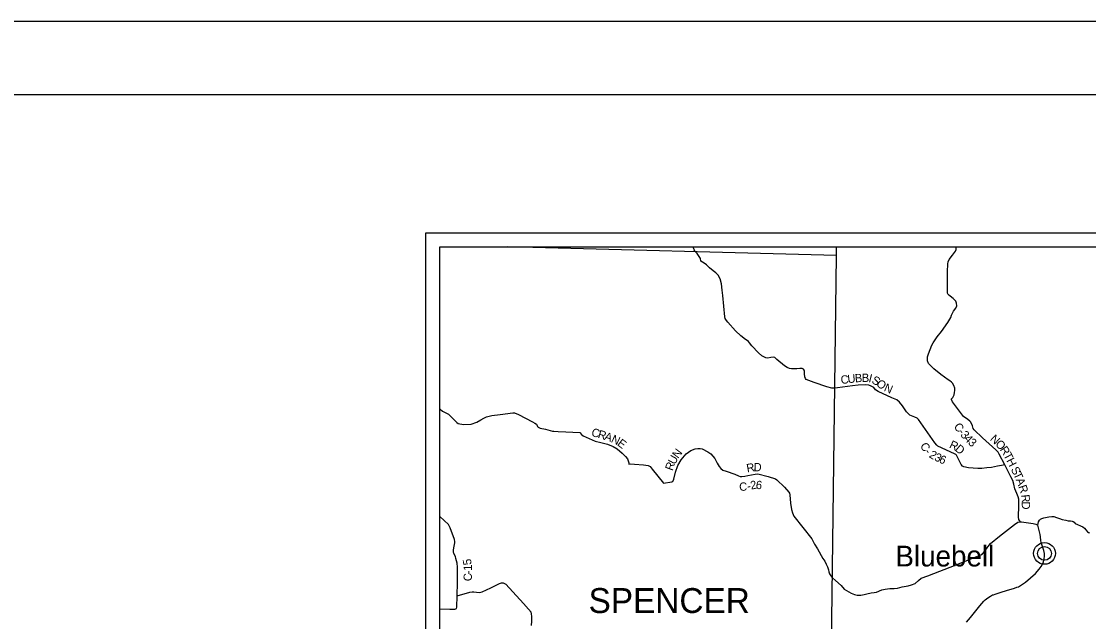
# Model space of a CAD drawing. Extents: x 0 to 34, y 0 to 22.
# Drawn here: x 17 to 24.28, y 17.9 to 22 of the extents above; entities that cross this region are included whole.
import ezdxf

# ---------------------------------------------------------------- set-up
doc = ezdxf.new("R2010")
doc.units = 0
for name, color, linetype in [('Default', 7, 'Continuous'), ('GM_X_County_Road', 7, 'Continuous'), ('GM_X_County_Road_Text', 7, 'Continuous'), ('GM_X_State_Route', 7, 'Continuous'), ('GM_X_Township', 7, 'Continuous'), ('GM_X_Township_Text', 7, 'Continuous'), ('GM_X_Unincorporated', 7, 'Continuous'), ('GM_X_Unincorporated_Text', 7, 'Continuous'), ('SH_Border', 7, 'Continuous'), ('SH_Cut_Line', 7, 'Continuous')]:
    doc.layers.add(name, color=color, linetype=linetype)

msp = doc.modelspace()

# ---------------------------------------------------------------- linework, layer by layer
at = {"layer": 'Default'}
for p, q in [((19.8526, 20.4625), (30.697, 20.4625)), ((19.8526, 9.6182), (19.8526, 20.4625))]:
    msp.add_line(p, q, dxfattribs=at)
msp.add_lwpolyline([(19.7581, 20.557), (30.7915, 20.557), (30.7915, 9.5237), (19.7581, 9.5237)], close=True, dxfattribs=at)
for points in [[(23.1773, 19.6971), (23.1785, 19.7118), (23.1846, 19.7322), (23.2089, 19.7911), (23.2169, 19.8062), (23.2449, 19.847), (23.2733, 19.885), (23.3165, 19.9446), (23.3377, 19.9797), (23.343, 19.9948), (23.3548, 20.0224), (23.3714, 20.0427), (23.3779, 20.0582), (23.3768, 20.0775), (23.3716, 20.0908), (23.3647, 20.0975), (23.3532, 20.1086), (23.3321, 20.1261), (23.3224, 20.1333), (23.3186, 20.1367), (23.3156, 20.1451), (23.3142, 20.161), (23.3142, 20.2018), (23.3142, 20.2911), (23.3163, 20.3448), (23.319, 20.3584), (23.3269, 20.3746), (23.3485, 20.4055), (23.3682, 20.4331), (23.3728, 20.4425), (23.3743, 20.4557), (23.3742, 20.4625)], [(22.5284, 19.4972), (22.527, 19.4972), (22.4928, 19.5061), (22.4048, 19.537), (22.3519, 19.5565), (22.3459, 19.563), (22.3414, 19.5751), (22.3399, 19.5948), (22.3388, 19.613), (22.337, 19.6205), (22.3336, 19.6266), (22.3245, 19.6312), (22.3161, 19.632), (22.3083, 19.6324), (22.2879, 19.6287), (22.2521, 19.6299), (22.2374, 19.6319), (22.2219, 19.638), (22.2035, 19.649), (22.1511, 19.6935), (22.1368, 19.7064), (22.1259, 19.7091), (22.1097, 19.7076), (22.0897, 19.7024), (22.0768, 19.704), (22.049, 19.7181), (22.0252, 19.739), (21.9816, 19.7861), (21.9654, 19.8073), (21.9571, 19.8168), (21.9484, 19.8233), (21.9368, 19.8294), (21.9066, 19.8543), (21.8694, 19.8898), (21.8167, 19.9478), (21.8073, 19.9582), (21.7982, 19.9733), (21.7971, 19.9851), (21.7839, 20.129), (21.7787, 20.165), (21.7731, 20.2089), (21.7637, 20.2438), (21.7513, 20.2673), (21.734, 20.2844), (21.7163, 20.2985), (21.6922, 20.3183), (21.6704, 20.338), (21.6545, 20.3506), (21.6338, 20.3635), (21.6298, 20.3832), (21.6221, 20.3965), (21.6083, 20.4171), (21.5937, 20.4302), (21.5864, 20.4436), (21.5852, 20.4482)], [(23.8134, 18.5861), (23.8049, 18.5953), (23.8004, 18.6025), (23.7982, 18.6176), (23.8007, 18.6962), (23.8005, 18.7397), (23.7975, 18.7571), (23.7878, 18.7787), (23.774, 18.8105), (23.7665, 18.8427), (23.7594, 18.868), (23.746, 18.8938), (23.7047, 18.9744), (23.6666, 19.048), (23.6599, 19.0616), (23.6433, 19.0768), (23.5531, 19.1595), (23.496, 19.2127), (23.4897, 19.2229), (23.4844, 19.2396), (23.4732, 19.2661), (23.4672, 19.2733), (23.4522, 19.2832), (23.424, 19.3052), (23.3497, 19.4038), (23.3426, 19.4193), (23.343, 19.4242), (23.3505, 19.4344), (23.3604, 19.4518), (23.3631, 19.468), (23.3639, 19.4809), (23.3636, 19.4975), (23.3572, 19.5168), (23.3486, 19.5312), (23.3422, 19.5392), (23.3317, 19.5468), (23.3189, 19.5536), (23.2681, 19.5897), (23.2208, 19.6304), (23.1858, 19.6657), (23.178, 19.6842), (23.1773, 19.6971)], [(23.7047, 18.9744), (23.6833, 18.9704), (23.6546, 18.9656), (23.6143, 18.9567), (23.5818, 18.9534), (23.5479, 18.9497), (23.5211, 18.9502), (23.4586, 18.955), (23.425, 18.9619), (23.4171, 18.9657), (23.4074, 18.976), (23.3913, 19.0097), (23.3804, 19.032), (23.3756, 19.0404), (23.3707, 19.0453), (23.3616, 19.0502), (23.2495, 19.1017), (23.2412, 19.1085), (23.2281, 19.1252), (23.1159, 19.2848), (23.1069, 19.292), (23.0919, 19.2993), (23.0572, 19.3145), (23.0347, 19.335), (23.0088, 19.376), (22.9882, 19.4029), (22.9698, 19.4188), (22.9347, 19.4314), (22.8417, 19.4737), (22.8237, 19.4865), (22.8119, 19.5011), (22.7934, 19.5123), (22.7788, 19.5174), (22.7547, 19.5196), (22.7048, 19.5179), (22.6678, 19.514), (22.5657, 19.4994), (22.5455, 19.4972), (22.5284, 19.4972)], [(19.8526, 19.3572), (19.8552, 19.3539), (19.8715, 19.3411), (19.8953, 19.3303), (19.9135, 19.3198), (19.9382, 19.2957), (19.9683, 19.2637), (19.9788, 19.2576), (20.0144, 19.2503), (20.0665, 19.2514), (20.1049, 19.2652), (20.1338, 19.2817), (20.1526, 19.2935), (20.1707, 19.3016), (20.2068, 19.3113), (20.2657, 19.3169), (20.3513, 19.3295), (20.3633, 19.3288), (20.3895, 19.318), (20.4849, 19.2671), (20.502, 19.2589), (20.5114, 19.2521), (20.5202, 19.2362), (20.5233, 19.2306), (20.538, 19.2242), (20.5736, 19.218), (20.6061, 19.2095), (20.6205, 19.2043), (20.6307, 19.2036), (20.6612, 19.203), (20.7118, 19.2006), (20.8085, 19.1944), (20.8184, 19.182), (20.8305, 19.1722), (20.8718, 19.1543), (20.9126, 19.1371), (20.9516, 19.1275), (20.9958, 19.1164), (21.0359, 19.1003), (21.0617, 19.0838), (21.0963, 19.0541), (21.1194, 19.0323), (21.1331, 19.0157), (21.1424, 18.9889), (21.1424, 18.9795), (21.1501, 18.9803), (21.1806, 18.9782), (21.2417, 18.9755), (21.2731, 18.9711), (21.2875, 18.9633), (21.3019, 18.9452), (21.3777, 18.8502), (21.4358, 18.8581), (21.4418, 18.8616), (21.4488, 18.8771), (21.4606, 18.9234), (21.4769, 18.9708), (21.4989, 19.008), (21.5333, 19.0502), (21.5637, 19.0724), (21.5938, 19.0846), (21.6133, 19.087), (21.6284, 19.087), (21.6409, 19.0831), (21.6808, 19.0626), (21.7015, 19.0489), (21.7158, 19.0344), (21.7282, 19.017), (21.7444, 18.9863), (21.7576, 18.9635), (21.7688, 18.9506), (21.7835, 18.9377), (21.8065, 18.9308), (21.8653, 18.9113), (21.8894, 18.9006), (21.9004, 18.8953), (21.9124, 18.8941), (21.9332, 18.8967), (21.9532, 18.9011), (22.0023, 18.9104), (22.0226, 18.9122), (22.0913, 18.8957), (22.1429, 18.8785), (22.152, 18.8732), (22.2032, 18.8227), (22.2325, 18.7889), (22.2381, 18.7805), (22.24, 18.7703), (22.2433, 18.7135), (22.2511, 18.6688), (22.2578, 18.6461), (22.2672, 18.6253), (22.3887, 18.4691), (22.4076, 18.4345), (22.4274, 18.4006), (22.4648, 18.3353), (22.4774, 18.3175), (22.4881, 18.2976), (22.4964, 18.2783), (22.5022, 18.2584), (22.5062, 18.244), (22.5111, 18.232), (22.5197, 18.2182), (22.5285, 18.2069), (22.5305, 18.2048)], [(19.972, 18.0798), (19.9729, 18.1729), (19.9744, 18.2758), (19.9712, 18.3038), (19.963, 18.3363), (19.9592, 18.3496), (19.9492, 18.3692), (19.9465, 18.3801), (19.9457, 18.3915), (19.9497, 18.4093), (19.9563, 18.4419), (19.9558, 18.4517), (19.9531, 18.4657), (19.9242, 18.5454), (19.9177, 18.5594), (19.9116, 18.5677), (19.8535, 18.6226), (19.8526, 18.6234)], [(22.5305, 18.2048), (22.5502, 18.1846), (22.5886, 18.1507), (22.6094, 18.1263), (22.6585, 18.0995), (22.6816, 18.0902), (22.6981, 18.0856), (22.7096, 18.0849), (22.7231, 18.086), (22.7473, 18.0906), (22.7657, 18.0956), (22.7953, 18.1014), (22.8153, 18.1037), (22.8302, 18.1068), (22.8671, 18.121), (22.889, 18.1267), (22.9213, 18.13), (22.9505, 18.13), (22.9727, 18.1338), (23.005, 18.1415), (23.0472, 18.1492), (23.0703, 18.1554), (23.0933, 18.1653), (23.1164, 18.1861), (23.1356, 18.2022), (23.1801, 18.2181), (23.3733, 18.2929), (23.5428, 18.3607), (23.5534, 18.3675), (23.5682, 18.3845), (23.5853, 18.408), (23.592, 18.4173), (23.6075, 18.4376), (23.6695, 18.4888), (23.7724, 18.5686), (23.7939, 18.5836), (23.8045, 18.5866), (23.8134, 18.5861)], [(23.8134, 18.5861), (23.8199, 18.5858), (23.8991, 18.5742)], [(23.8991, 18.5742), (23.8994, 18.5741), (23.9167, 18.5699), (23.9315, 18.5627)], [(19.8526, 17.9925), (19.9217, 17.9902), (19.9462, 17.9899), (19.9564, 17.9904), (19.9624, 17.9919), (19.9665, 17.9953), (19.9695, 18.0029), (19.972, 18.0798), (20.0586, 18.1049), (20.0733, 18.108), (20.085, 18.1073), (20.1039, 18.1059), (20.1254, 18.1038), (20.1428, 18.1076), (20.2018, 18.1349), (20.2609, 18.1647), (20.2729, 18.1697), (20.285, 18.169), (20.3024, 18.1601), (20.3515, 18.1089), (20.4241, 18.0291), (20.4579, 17.9903), (20.4762, 17.9703)], [(20.4777, 17.878), (20.4804, 17.909), (20.4811, 17.94), (20.4783, 17.9589), (20.4762, 17.9703)]]:
    msp.add_lwpolyline(points, dxfattribs=at)
at = {"layer": 'GM_X_County_Road'}
msp.add_lwpolyline([(21.5852, 20.4482), (21.5833, 20.455), (21.5816, 20.4625)], dxfattribs=at)
at = {"layer": 'GM_X_State_Route'}
msp.add_lwpolyline([(23.4452, 17.9024), (23.4705, 17.9333), (23.4988, 17.967), (23.5361, 18.0129), (23.5614, 18.0438), (23.5715, 18.0542), (23.5902, 18.068), (23.6083, 18.0796), (23.6218, 18.0866), (23.6281, 18.0888), (23.6395, 18.0928), (23.6809, 18.1066), (23.7178, 18.1169), (23.771, 18.133), (23.7883, 18.1389), (23.7988, 18.1432), (23.8135, 18.1525), (23.8461, 18.1748), (23.8817, 18.2029), (23.9138, 18.2339), (23.9392, 18.2622), (23.953, 18.2806), (23.9619, 18.2962), (23.9684, 18.3133), (23.9739, 18.3327), (23.9767, 18.3513), (23.9761, 18.3706), (23.9713, 18.3898), (23.9599, 18.4249), (23.954, 18.4445), (23.9519, 18.4578), (23.9497, 18.4827), (23.9465, 18.4986), (23.9417, 18.5171), (23.9342, 18.5458), (23.9315, 18.5627), (23.932, 18.5742), (23.9352, 18.5855), (23.9419, 18.5966), (23.9486, 18.6046), (23.9573, 18.6089), (23.9723, 18.6133), (24.0067, 18.619), (24.0252, 18.6222), (24.0392, 18.6216), (24.0582, 18.6158), (24.0783, 18.6081), (24.0965, 18.6026), (24.1215, 18.5968), (24.1375, 18.5936), (24.1534, 18.5919), (24.1644, 18.5902), (24.1712, 18.5876), (24.1777, 18.5824), (24.1861, 18.5749), (24.2017, 18.5664), (24.2219, 18.5583), (24.2371, 18.5509), (24.2478, 18.5427), (24.2581, 18.5303), (24.2681, 18.5183), (24.275, 18.5138), (24.2833, 18.5102)], dxfattribs=at)
at = {"layer": 'GM_X_Township'}
for p, q in [((22.5575, 20.4019), (20.3145, 20.4625)), ((20.5897, 20.4554), (20.5109, 20.4596)), ((22.5575, 20.4019), (22.5582, 20.4625)), ((21.5937, 20.4302), (21.5815, 20.43)), ((22.5206, 17.4094), (22.5575, 20.4019))]:
    msp.add_line(p, q, dxfattribs=at)
at = {"layer": 'GM_X_Unincorporated'}
for radius in [0.0742, 0.0471]:
    msp.add_circle((23.9761, 18.3706), radius, dxfattribs=at)
at = {"layer": 'SH_Border'}
msp.add_lwpolyline([(1.5, 21.5), (33.5, 21.5), (33.5, 0.5), (1.5, 0.5)], close=True, dxfattribs=at)
at = {"layer": 'SH_Cut_Line'}
msp.add_lwpolyline([(0, 0), (34, 0), (34, 22), (0, 22)], close=True, dxfattribs=at)

# ---------------------------------------------------------------- texts
at = {"layer": 'GM_X_County_Road_Text'}
for s, rotation, p in [('C', 7.1652, (22.5899, 19.5251)), ('U', 6.9732, (22.6361, 19.5309)), ('B', 4.24439, (22.6849, 19.5369)), ('B', 359.23696, (22.73, 19.5403)), ('I', 346.10197, (22.7732, 19.5401)), ('S', 331.21814, (22.7922, 19.5359)), ('O', 322.15889, (22.8237, 19.5188)), ('N', 336.90262, (22.8768, 19.4801)), ('C', 343.12095, (20.8819, 19.1734)), ('R', 343.07346, (20.9264, 19.1599)), ('C', 307.96125, (23.3542, 19.2344)), ('A', 341.67391, (20.9706, 19.1464)), ('N', 334.47276, (21.0163, 19.1315)), ('E', 322.56441, (21.0586, 19.1116)), ('R', 334.4718, (23.3223, 19.0933)), ('-', 308.72655, (23.3834, 19.1971)), ('3', 310.75315, (23.3993, 19.1772)), ('4', 313.58149, (23.4242, 19.1485)), ('3', 317.07085, (23.4509, 19.1205)), ('N', 316.98896, (23.6005, 19.1461)), ('O', 313.68749, (23.6364, 19.1127)), ('N', 52.66928, (21.4777, 19.0137)), ('C', 304.56803, (23.1242, 19.1033)), ('-', 309.20704, (23.1536, 19.061)), ('2', 328.49868, (23.184, 19.0293)), ('D', 320.25553, (23.3612, 19.0752)), ('R', 303.68141, (23.6692, 19.0786)), ('T', 297.63839, (23.6942, 19.0412)), ('U', 61.15928, (21.4549, 18.9718)), ('3', 335.37773, (23.2203, 19.0075)), ('6', 335.63823, (23.2523, 18.9929)), ('H', 297.35357, (23.7139, 19.0037)), ('R', 69.82515, (21.4398, 18.9302)), ('R', 10.24323, (21.9493, 18.9228)), ('D', 359.53736, (21.9924, 18.9309)), ('S', 297.21105, (23.7448, 18.9439)), ('T', 294.8859, (23.762, 18.9104)), ('C', 2.25645, (21.8952, 18.7966)), ('2', 10.7277, (21.9757, 18.8054)), ('6', 353.0512, (22.0054, 18.8118)), ('A', 290.4484, (23.7794, 18.873)), ('-', 13.53284, (21.9538, 18.8001)), ('R', 288.84596, (23.7967, 18.8267)), ('R', 276.41821, (23.8164, 18.7691)), ('D', 269.22404, (23.8215, 18.7247)), ('5', 98.63472, (20.071, 18.2952)), ('1', 91.01139, (20.0723, 18.252)), ('C', 89.52382, (20.0718, 18.1806)), ('-', 89.77586, (20.0722, 18.2274))]:
    msp.add_text(s, height=0.0567, rotation=rotation, dxfattribs=at).set_placement(p)
at = {"layer": 'GM_X_Township_Text'}
msp.add_text('SPENCER', height=0.1701, rotation=0.00001, dxfattribs=at).set_placement((20.8673, 17.9636))
at = {"layer": 'GM_X_Unincorporated_Text'}
msp.add_text('Bluebell', height=0.14175, rotation=0.00001, dxfattribs=at).set_placement((22.9593, 18.2813))

doc.saveas('drawing.dxf')
